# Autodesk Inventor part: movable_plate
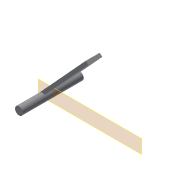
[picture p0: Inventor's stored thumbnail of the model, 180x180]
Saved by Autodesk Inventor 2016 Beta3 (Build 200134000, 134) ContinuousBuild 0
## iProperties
Created: 2016-03
Part Number: movable_plate
Material: Generic
Document SubType Name: Modeling
Designer: Gaurav
Density: 1 g/cm^3
Appearance: Default
Author: Gaurav
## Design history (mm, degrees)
workplane "Work Plane1"
sketch "Sketch2"
  geometry: L1 (-22.105, 11.375)-(36.065, 74.959); L2 (36.065, 74.959)-(39.28, 72.017); L3 (39.28, 72.017)-(-15.542, 12.092); A1 r 5 centre (-18.416, 8) between (-22.105, 11.375) and (-15.542, 12.092) reference; A2 r 5 centre (-18.416, 8) between (-13.416, 8) and (-18.416, 3) reference; A3 r 5 centre (-18.416, 8) between (-15.542, 12.092) and (-21.951, 11.536); 1 further point
  constraints: 6 end point, 5 point on circle, 1 centre point, 1 parallel, 1 perpendicular, 1 tangent
extrude "Extrusion2" join sketch "Sketch2" stored distance "d2" = 17.4625; taper "d3" = 0 deg
sketch "Sketch3"
  geometry: C1 r 5 at (-18.416, 8); A1 r 5 centre (-18.416, 8) between (-15.542, 12.092) and (-22.105, 11.375) reference; 1 further point
  constraints: 1 centre point, 1 coincident, 1 concentric
extrude "Extrusion3" join sketch "Sketch3" stored distance "d4" = 80.01; taper "d5" = 0 deg
body "Solid1"
node "Reference3"
